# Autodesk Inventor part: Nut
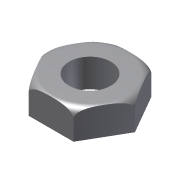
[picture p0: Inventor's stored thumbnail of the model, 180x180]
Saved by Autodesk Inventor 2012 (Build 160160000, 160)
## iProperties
Created: 2009-04
Part Number: Nut
Document SubType Name: Modeling
Designer: Sham
Density: 1 g/cm^3
Material: Default
Mass: 75.6707 g
Surface Area: 146.977 cm^2
Volume: 75.6707 cm^3
Author: Sham
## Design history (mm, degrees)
sketch "Sketch1"
  geometry: L1 (19.919, 34.5)-(39.837, 0); L2 (39.837, 0)-(19.919, -34.5); L3 (19.919, -34.5)-(-19.919, -34.5); L4 (-19.919, -34.5)-(-39.837, 0); L5 (-39.837, 0)-(-19.919, 34.5); L6 (-19.919, 34.5)-(19.919, 34.5); C1 r 18.5 at (0, 0); 1 further point
  constraints: 12 end point, 1 centre point, 1 coincident, 13 other
  dimensions: "d0" = 69 distance between parallel lines of L3 L6; "d1" = 37 diameter of C1
extrude "Extrusion1" new body sketch "Sketch1" distance "d2" = 25; taper "d3" = 0 deg
sketch "Sketch2"
  geometry: L1 (0, -5.4)-(0, 32.4) reference; L2 (-19.919, 25)-(-39.837, 25) reference; L3 (-19.919, 25)-(-39.837, 25) reference; L4 (-39.837, 0)-(-39.837, 25) reference; L5 (-19.919, 0)-(-39.837, 0) reference; L6 (-19.919, 0)-(-19.919, 25) reference; A1 r 7.5 centre (-32.337, 17.5) between (-32.337, 25) and (-39.837, 17.5); 1 further point
  constraints: 2 midpoint, 2 point on circle, 2 point on line, 2 tangent, 1 centre point
  dimensions: "d6" = 7.5 radius of A1
revolve "Revolution1" sketch "Sketch2" stored, may be unused: angle "d5" = 90 deg
body "Solid1"
node "Projected Loop1"
other parameters: "d4" = 90 deg
